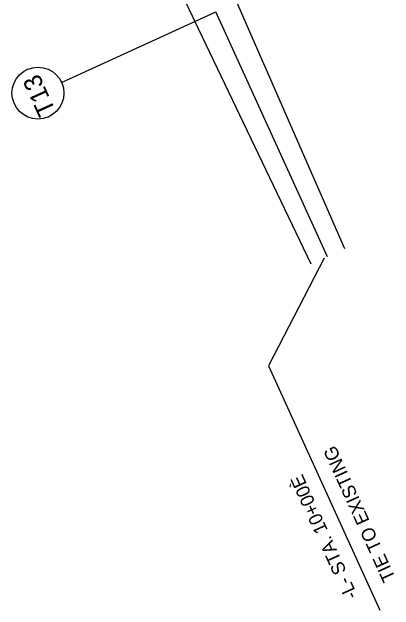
# Model space of a CAD drawing. Extents: x 1657109 to 2100937, y 684916 to 883211.
# Drawn here: x 2097924.6 to 2098123.3, y 684916.4 to 685227.5 of the extents above; entities that cross this region are included whole.
import ezdxf

# ---------------------------------------------------------------- set-up
doc = ezdxf.new("R2010")
doc.units = 0
for name, color, linetype in [('Prop CMT Pvmt Gravel', 7, 'Continuous'), ('Prop Guardrail Anchor Unit CELL', 7, 'Continuous'), ('Scratch_Level_1', 7, 'Continuous')]:
    doc.layers.add(name, color=color, linetype=linetype)

msp = doc.modelspace()

# ---------------------------------------------------------------- linework, layer by layer
at = {"layer": 'Prop CMT Pvmt Gravel'}
for p, q in [((2097950.45, 685190.77), (2098030.23, 685227.35)), ((2098086.88, 685099.31), (2098058, 685043.42)), ((2098058, 685043.42), (2098115.82, 684916.36))]:
    msp.add_line(p, q, dxfattribs=at)
msp.add_circle((2097938.13, 685185.25), 13.5, dxfattribs=at)
at = {"layer": 'Prop Guardrail Anchor Unit CELL'}
for p, q in [((2098097.63, 685104.2), (2098041.61, 685232.53)), ((2098080.26, 685096.3), (2098019.77, 685222.59))]:
    msp.add_line(p, q, dxfattribs=at)
msp.add_spline([(2098019.77, 685222.59), (2098019.34, 685223.48), (2098018.91, 685224.37), (2098018.48, 685225.27), (2098018.05, 685226.16), (2098017.62, 685227.05), (2098017.2, 685227.95), (2098016.77, 685228.84), (2098016.34, 685229.74), (2098015.91, 685230.63), (2098015.48, 685231.52), (2098015.06, 685232.42), (2098014.63, 685233.31), (2098014.2, 685234.2), (2098013.77, 685235.09), (2098013.34, 685235.98), (2098012.92, 685236.87), (2098012.49, 685237.76), (2098012.06, 685238.65), (2098011.63, 685239.55), (2098011.2, 685240.44), (2098010.77, 685241.33), (2098010.34, 685242.22), (2098009.91, 685243.11), (2098009.48, 685244), (2098009.05, 685244.89), (2098008.62, 685245.78), (2098008.19, 685246.67), (2098007.76, 685247.56), (2098007.33, 685248.45), (2098006.9, 685249.34), (2098006.47, 685250.23), (2098006.04, 685251.12), (2098005.61, 685252.01), (2098005.18, 685252.9), (2098004.74, 685253.79), (2098004.31, 685254.68), (2098003.88, 685255.57), (2098003.45, 685256.46), (2098003.02, 685257.34), (2098002.58, 685258.23), (2098002.15, 685259.12), (2098001.72, 685260.01), (2098001.28, 685260.9), (2098000.85, 685261.79), (2098000.42, 685262.68), (2097999.98, 685263.57), (2097999.55, 685264.45), (2097999.12, 685265.34), (2097998.68, 685266.23), (2097998.25, 685267.12), (2097997.81, 685268.01), (2097997.38, 685268.89), (2097996.94, 685269.78), (2097996.51, 685270.67), (2097996.07, 685271.56), (2097995.64, 685272.45), (2097995.2, 685273.33), (2097994.77, 685274.22), (2097994.33, 685275.11), (2097993.9, 685276), (2097993.46, 685276.88), (2097993.02, 685277.77), (2097992.59, 685278.66), (2097992.15, 685279.54), (2097991.71, 685280.43), (2097991.28, 685281.32), (2097990.84, 685282.2), (2097990.4, 685283.09), (2097989.96, 685283.98), (2097989.53, 685284.86), (2097989.09, 685285.75), (2097988.65, 685286.63), (2097988.21, 685287.52), (2097987.77, 685288.41)], degree=3, dxfattribs=at)
at = {"layer": 'Scratch_Level_1'}
msp.add_line((2098088.67, 685100.13), (2098030.69, 685227.56), dxfattribs=at)

# ---------------------------------------------------------------- texts
at = {"layer": 'Prop CMT Pvmt Gravel'}
for s, height, p in [('T13', 9.45, (2097947.55, 685175.95)), ('TIE TO EXISTING', 7, (2098124.26, 684932.92)), ('-L- STA. 10+00È', 7, (2098104.48, 684923.84))]:
    msp.add_text(s, height=height, rotation=114.4674, dxfattribs=at).set_placement(p)

doc.saveas('drawing.dxf')
